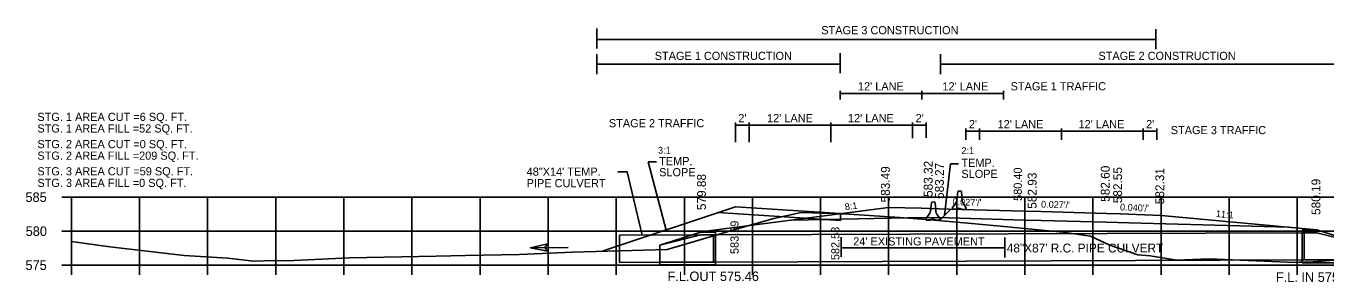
# Model space of a CAD drawing. Extents: x 642114 to 642416, y 286928 to 293347.
# Drawn here: x 642113.6 to 642304.3, y 288135.3 to 288172.9 of the extents above; entities that cross this region are included whole.
import ezdxf

# ---------------------------------------------------------------- set-up
doc = ezdxf.new("R2010")
doc.units = 0
for name, color, linetype in [('59', 7, 'Continuous'), ('Level 43', 7, 'Continuous'), ('Level 58', 7, 'Continuous'), ('R_Axis', 7, 'Continuous'), ('R_Axis Annot', 7, 'Continuous'), ('R_Draft', 7, 'Continuous'), ('R_Exist Surface', 7, 'Continuous'), ('R_Fin Surface', 7, 'Continuous'), ('R_Grid', 7, 'Continuous'), ('R_MOT Barrier', 7, 'Continuous'), ('R_Water', 7, 'Continuous'), ('R_Xsect Elev', 7, 'Continuous'), ('R_Xsect Slope', 7, 'Continuous')]:
    doc.layers.add(name, color=color, linetype=linetype)

# ---------------------------------------------------------------- blocks, each defined once
blk = doc.blocks.new('BARRIER WALL X-SECTION')
at = {"layer": 'R_MOT Barrier'}
for p, q in [((0.8, 2.59), (0.63, 1.29)), ((0.8, 2.59), (0.87, 2.65)), ((0.87, 2.65), (1.24, 2.64)), ((1.24, 2.64), (1.31, 2.58)), ((1.31, 2.58), (1.42, 1.27)), ((0.48, 0.9), (0, 0.25)), ((0, 0.25), (0, 0)), ((0.5, -0.01), (0, 0)), ((0.5, -0.01), (1, 0.15)), ((1, 0.15), (1.5, -0.03)), ((1.56, 0.88), (2, 0.21)), ((2, 0.21), (2, -0.04)), ((1.5, -0.03), (2, -0.04))]:
    blk.add_line(p, q, dxfattribs=at)
for centre, start, end in [((-0.2, 1.39), 323.8622, 352.8452), ((2.25, 1.34), 184.8632, 213.8462)]:
    blk.add_arc(centre, 0.833, start, end, dxfattribs=at)
blk = doc.blocks.new('FES 48 X-SECTION')
at = {"layer": 'R_Water'}
for p, q in [((-7.876, 2.5), (-1.876, 4.416)), ((-1.876, 4), (-7.876, 2.5)), ((-1.876, 4.416), (0.291, 4.416)), ((-1.876, 4), (0.291, 4)), ((0, 0), (0, 4)), ((0.291, -0.417), (0.291, 4.416)), ((-7.876, 2.5), (-7.876, -0.417)), ((-7.876, 0), (0.291, 0)), ((-7.876, -0.417), (0.291, -0.417))]:
    blk.add_line(p, q, dxfattribs=at)
blk = doc.blocks.new('FA')
at = {"layer": 'Level 43'}
blk.add_lwpolyline([(7.94, 0), (0, 0)], dxfattribs=at)
at = {"layer": 'Level 58'}
blk.add_lwpolyline([(4.34, 0.75), (7.94, 0), (4.34, -0.75), (4.94, 0)], close=True, dxfattribs=at)

msp = doc.modelspace()

# ---------------------------------------------------------------- linework, layer by layer
at = {"layer": 'R_Axis'}
for p, q in [((642118.84, 288147.73), (642120.24, 288147.73)), ((642120.24, 288137.73), (642120.24, 288147.73)), ((642118.84, 288142.73), (642120.24, 288142.73)), ((642118.84, 288137.73), (642120.24, 288137.73)), ((642120.24, 288137.73), (642400.24, 288137.73)), ((642120.24, 288136.33), (642120.24, 288137.73)), ((642130.24, 288136.33), (642130.24, 288137.73)), ((642140.24, 288136.33), (642140.24, 288137.73)), ((642150.24, 288136.33), (642150.24, 288137.73)), ((642160.24, 288136.33), (642160.24, 288137.73)), ((642170.24, 288136.33), (642170.24, 288137.73)), ((642180.24, 288136.33), (642180.24, 288137.73)), ((642190.24, 288136.33), (642190.24, 288137.73)), ((642200.24, 288136.33), (642200.24, 288137.73)), ((642210.24, 288136.33), (642210.24, 288137.73)), ((642220.24, 288136.33), (642220.24, 288137.73)), ((642230.24, 288136.33), (642230.24, 288137.73)), ((642240.24, 288136.33), (642240.24, 288137.73)), ((642250.24, 288136.33), (642250.24, 288137.73)), ((642260.24, 288136.33), (642260.24, 288137.73)), ((642270.24, 288136.33), (642270.24, 288137.73)), ((642280.24, 288136.33), (642280.24, 288137.73)), ((642290.24, 288136.33), (642290.24, 288137.73)), ((642300.24, 288136.33), (642300.24, 288137.73))]:
    msp.add_line(p, q, dxfattribs=at)
at = {"layer": 'R_Exist Surface'}
for points in [[(642120.24, 288141.22), (642125.89, 288140.44), (642136.8, 288139.15), (642143.19, 288138.77), (642146.98, 288138.34), (642150.12, 288138.43), (642151.85, 288138.37), (642161.07, 288138.8), (642173.81, 288139.04), (642178.1, 288139.14), (642186.03, 288139.3), (642193.81, 288139.65), (642207.73, 288140.02), (642218.18, 288143.12), (642221.99, 288144.21), (642223.36, 288144.57), (642227.4, 288145.49), (642232.07, 288145.33), (642234.38, 288145.24), (642241.88, 288144.76), (642245.82, 288144.47), (642251.87, 288143.93), (642256.68, 288143.48), (642261.72, 288142.99), (642264.26, 288142.74), (642265.8, 288142.58), (642269.88, 288141.98), (642272.7, 288140.69), (642276.82, 288139.24), (642278.62, 288139.11), (642282.58, 288138.48), (642287.27, 288138.65), (642299.95, 288138.11), (642300.57, 288138.16), (642300.88, 288138.16), (642302, 288138.16), (642316, 288139.29)], [(642226.01, 288144.36), (642242.94, 288144.7), (642246.24, 288144.76), (642249.07, 288144.69), (642260.24, 288144.37), (642262.66, 288144.31), (642272.24, 288144.04), (642275.53, 288143.95), (642299.03, 288143.3)]]:
    msp.add_lwpolyline(points, dxfattribs=at)
at = {"layer": 'R_Fin Surface'}
msp.add_lwpolyline([(642212.65, 288142.61), (642240.24, 288146.22), (642245.05, 288146.09), (642246.24, 288146.05), (642249.07, 288145.98), (642260.24, 288145.67), (642262.66, 288145.6), (642272.24, 288145.33), (642274.24, 288145.28), (642280.24, 288145.04), (642303.12, 288142.92)], dxfattribs=at)
at = {"layer": 'R_Grid'}
for p, q in [((642120.24, 288147.73), (642400.24, 288147.73)), ((642120.24, 288137.73), (642120.24, 288147.73)), ((642130.24, 288137.73), (642130.24, 288147.73)), ((642140.24, 288137.73), (642140.24, 288147.73)), ((642150.24, 288137.73), (642150.24, 288147.73)), ((642160.24, 288137.73), (642160.24, 288147.73)), ((642170.24, 288137.73), (642170.24, 288147.73)), ((642180.24, 288137.73), (642180.24, 288147.73)), ((642190.24, 288137.73), (642190.24, 288147.73)), ((642200.24, 288137.73), (642200.24, 288147.73)), ((642210.24, 288137.73), (642210.24, 288147.73)), ((642220.24, 288137.73), (642220.24, 288147.73)), ((642230.24, 288137.73), (642230.24, 288147.73)), ((642240.24, 288137.73), (642240.24, 288147.73)), ((642250.24, 288137.73), (642250.24, 288147.73)), ((642260.24, 288137.73), (642260.24, 288147.73)), ((642270.24, 288137.73), (642270.24, 288147.73)), ((642280.24, 288137.73), (642280.24, 288147.73)), ((642290.24, 288137.73), (642290.24, 288147.73)), ((642300.24, 288137.73), (642300.24, 288147.73)), ((642120.24, 288142.73), (642400.24, 288142.73)), ((642120.24, 288137.73), (642400.24, 288137.73))]:
    msp.add_line(p, q, dxfattribs=at)
at = {"layer": 'R_Water'}
for points in [[(642200.74, 288142.14), (642214.51, 288142.19)], [(642200.74, 288138.14), (642200.74, 288142.14)], [(642214.51, 288142.19), (642301.23, 288142.5)], [(642200.74, 288138.14), (642214.52, 288138.19)], [(642214.52, 288138.19), (642301.24, 288138.5)]]:
    msp.add_lwpolyline(points, dxfattribs=at)
at = {"layer": 'R_Xsect Elev'}
for p, q in [((642197.4, 288169.59), (642197.4, 288172.51)), ((642279.49, 288169.48), (642279.49, 288172.41)), ((642197.4, 288170.92), (642279.49, 288170.92)), ((642197.4, 288165.81), (642197.4, 288168.74)), ((642233.12, 288165.96), (642233.12, 288168.89)), ((642247.88, 288165.81), (642247.88, 288168.74)), ((642197.4, 288167.28), (642233.12, 288167.28)), ((642247.88, 288167.28), (642309.86, 288167.28)), ((642233.12, 288162.06), (642233.12, 288163.38)), ((642233.12, 288162.96), (642257.12, 288162.96)), ((642245.12, 288162.06), (642245.12, 288163.38)), ((642257.12, 288162.06), (642257.12, 288163.38)), ((642217.74, 288155.83), (642217.74, 288158.71)), ((642217.74, 288158.29), (642245.74, 288158.29)), ((642219.74, 288155.83), (642219.74, 288158.71)), ((642231.74, 288155.83), (642231.74, 288158.71)), ((642243.74, 288156.38), (642243.74, 288158.71)), ((642245.74, 288156.43), (642245.74, 288158.71)), ((642251.6, 288156.16), (642251.6, 288157.82)), ((642251.6, 288157.41), (642279.6, 288157.41)), ((642253.6, 288156.16), (642253.6, 288157.82)), ((642265.6, 288156.16), (642265.6, 288157.82)), ((642277.6, 288156.16), (642277.6, 288157.82)), ((642279.6, 288156.16), (642279.6, 288157.82)), ((642198.05, 288139.76), (642217.74, 288146.32)), ((642233.19, 288144.32), (642215.18, 288145.47)), ((642233.19, 288145.33), (642217.74, 288146.32)), ((642247.74, 288144.33), (642249.38, 288145.97)), ((642233.19, 288145.32), (642233.19, 288144.32)), ((642233.29, 288138.94), (642233.29, 288141.87)), ((642257.29, 288138.85), (642257.29, 288141.78)), ((642233.29, 288140.29), (642257.29, 288140.29))]:
    msp.add_line(p, q, dxfattribs=at)
for points in [[(642204.05, 288142.15), (642201.86, 288151.43), (642200.48, 288151.43)], [(642204.92, 288152.9), (642207.59, 288142.88)], [(642206.14, 288152.9), (642204.92, 288152.9)], [(642249.3, 288152.65), (642248.46, 288145.06)], [(642250.52, 288152.65), (642249.3, 288152.65)]]:
    msp.add_lwpolyline(points, dxfattribs=at)

# ---------------------------------------------------------------- block references
at = {"layer": 'R_Water'}
msp.add_blockref('FES 48 X-SECTION', (642214.52, 288138.19), dxfattribs=at)
at = {"layer": 'R_Water', "yscale": -1, "rotation": 180}
msp.add_blockref('FES 48 X-SECTION', (642301.24, 288138.5), dxfattribs=at)
at = {"layer": 'R_Xsect Elev'}
for p in [(642249.61, 288145.96), (642245.74, 288144.37)]:
    msp.add_blockref('BARRIER WALL X-SECTION', p, dxfattribs=at)
at = {"layer": 'R_Xsect Elev', "xscale": 0.7000000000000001, "yscale": 0.6999999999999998, "rotation": -179.4648050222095}
msp.add_blockref('FA', (642193.19, 288140.35), dxfattribs=at)

# ---------------------------------------------------------------- texts
at = {"layer": '59'}
for s, height, p in [('48"X14\' TEMP.', 1.2, (642187.09, 288150.88)), ('PIPE CULVERT', 1.2, (642187.09, 288149.19)), ('48"X87\' R.C. PIPE CULVERT', 1.3, (642257.59, 288139.6)), ('F.L.OUT 575.46', 1.4, (642207.77, 288135.4)), ('F.L. IN 575.77', 1.4, (642297.11, 288135.27))]:
    msp.add_text(s, height=height, dxfattribs=at).set_placement(p)
for s, p in [(' 583.49', (642240.41, 288146.47)), (' 583.32', (642246.7, 288147.28)), (' 583.27', (642248.35, 288146.98)), (' 582.93', (642261.96, 288145.54)), (' 582.60', (642272.7, 288146.56)), (' 582.55', (642274.52, 288146.35)), (' 582.31', (642280.7, 288146.21)), (' 579.88', (642213.41, 288145.34)), (' 580.19', (642303.64, 288144.63))]:
    msp.add_text(s, height=1.3, rotation=90, dxfattribs=at).set_placement(p)
at = {"layer": 'R_Axis Annot'}
for s, p in [('585', (642113.49, 288147.03)), ('580', (642113.52, 288142.03)), ('575', (642113.49, 288137.03))]:
    msp.add_text(s, height=1.4, dxfattribs=at).set_placement(p)
at = {"layer": 'R_Draft'}
for s, p in [('STG. 1 AREA CUT =6 SQ. FT.', (642115.24, 288158.93)), ('STG. 1 AREA FILL =52 SQ. FT.', (642115.24, 288157.23)), ('STG. 2 AREA CUT =0 SQ. FT.', (642115.24, 288154.93)), ('STG. 2 AREA FILL =209 SQ. FT.', (642115.24, 288153.23)), ('STG. 3 AREA CUT =59 SQ. FT.', (642115.24, 288150.93)), ('STG. 3 AREA FILL =0 SQ. FT.', (642115.24, 288149.23))]:
    msp.add_text(s, height=1.2, dxfattribs=at).set_placement(p)
at = {"layer": 'R_Xsect Elev'}
for s, p in [('STAGE 3 CONSTRUCTION', (642230.35, 288171.67)), ('STAGE 1 CONSTRUCTION', (642205.89, 288167.9)), ('STAGE 2 CONSTRUCTION', (642271.05, 288167.9)), ("12' LANE", (642235.74, 288163.42)), ("12' LANE", (642248.14, 288163.42)), ('STAGE 1 TRAFFIC', (642258.16, 288163.43)), ('STAGE 2 TRAFFIC', (642199.16, 288158)), ("2'", (642218.17, 288158.75)), ("12' LANE", (642222.39, 288158.75)), ("12' LANE", (642234.27, 288158.75)), ("2'", (642244.2, 288158.75)), ("2'", (642252.02, 288157.86)), ("12' LANE", (642256.24, 288157.86)), ("12' LANE", (642268.12, 288157.86)), ("2'", (642278.05, 288157.86)), ('STAGE 3 TRAFFIC', (642281.67, 288156.99)), ('TEMP.', (642206.54, 288152.43)), ('TEMP.', (642250.92, 288152.17)), ('SLOPE', (642206.54, 288150.8)), ('SLOPE', (642250.92, 288150.55)), ("24' EXISTING PAVEMENT", (642235.04, 288140.63))]:
    msp.add_text(s, height=1.2, dxfattribs=at).set_placement(p)
for s, p in [('580.40', (642259.8, 288147.18)), ('583.59', (642218.21, 288139.37)), ('582.58', (642233.01, 288138.47))]:
    msp.add_text(s, height=1.2, rotation=90, dxfattribs=at).set_placement(p)
at = {"layer": 'R_Xsect Slope'}
for s, rotation, p in [('3:1', 0.32, (642206.38, 288154.12)), ('2:1', 0.32, (642250.93, 288154.07)), ("0.027'/'", 358.4135, (642249.61, 288146.56)), ('8:1', 7.4375, (642233.87, 288145.8)), ("0.027'/'", 358.4135, (642262.61, 288146.2)), ("0.040'/'", 357.5318, (642274.2, 288145.79)), ('11:1', 354.6012, (642288.26, 288144.83))]:
    msp.add_text(s, height=1, rotation=rotation, dxfattribs=at).set_placement(p)

doc.saveas('drawing.dxf')
